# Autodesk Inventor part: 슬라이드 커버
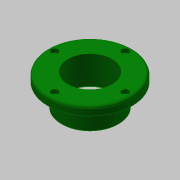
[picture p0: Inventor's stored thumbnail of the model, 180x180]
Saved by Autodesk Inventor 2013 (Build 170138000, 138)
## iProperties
Created: 2015-10
Part Number: 슬라이드 커버
Document SubType Name: Modeling
Designer: mdu
Density: 2.71 g/cm^3
Material: 알루미늄 6061
Mass: 221.924 g
Surface Area: 243.242 cm^2
Volume: 81.8907 cm^3
Author: mdu
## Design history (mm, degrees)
sketch "스케치1"
  geometry: C1 r 47.5 at (0, 0); C2 r 32.5 at (0, 0); 1 further point
  constraints: 2 centre point, 2 coincident
  dimensions: "d33" = 95 diameter of C1; "d35" = 65 diameter of C2
extrude "돌출1" new body sketch "스케치1" distance "d0" = 10; taper "d1" = 0 deg
extrude "돌출2" join sketch "스케치1" distance "d2" = 26; taper "d3" = 0 deg
hole "구멍1" diameter "d6" = 50; stored, may be unused: countersink angle "d10" = 90 deg, drill point angle "d12" = 118 deg; dims "d4" = 10, "d5" = 10, "d7" = 6, "d8" = 4, "d9" = 2, "d11" = 8
sketch "스케치2" dims "d36" = 80
  geometry: 4 further points
  constraints: 2 coincident, 2 vertical alignment, 2 other
hole "구멍2" sketch "스케치2" at (0, 40) diameter "d13" = 4.5; stored, may be unused: countersink angle "d17" = 90 deg, drill point angle "d19" = 118 deg; dims "d14" = 6, "d15" = 8, "d16" = 4.4, "d18" = 8
fillet "모깎기1" dims "d23" = 3
chamfer "모따기1" distance "d24" = 1; stored, may be unused: second distance "d25" = 2, angle "d26" = 45 deg
sketch "스케치3"
  geometry: C1 r 25 at (0, 0); C2 r 30 at (0, 0); C3 r 26 at (0, 0) reference; 1 further point
  constraints: 2 centre point, 2 coincident
  dimensions: "d27" = 60 diameter of C2
extrude "돌출3" cut sketch "스케치3" distance "d28" = 3; taper "d29" = 0 deg
chamfer "모따기2" distance "d30" = 1; stored, may be unused: second distance "d31" = 2, angle "d32" = 45 deg
node "솔리드1"
pattern_circular "원형 패턴1" dims angle "d21" = 360 deg
